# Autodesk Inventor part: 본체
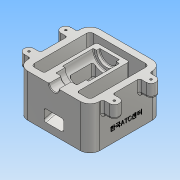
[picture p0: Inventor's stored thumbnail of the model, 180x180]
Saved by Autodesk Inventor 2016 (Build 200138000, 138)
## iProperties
Created: 2018-01
Part Number: 본체
Material: 알루미늄 6061
Document SubType Name: Modeling
Designer: Administrator
Density: 2.7 g/cm^3
Appearance: 알루미늄 - 평지
Mass: 994.61 g
Surface Area: 834.489 cm^2
Volume: 368.374 cm^3
Author: Administrator
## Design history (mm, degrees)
sketch "스케치1"
  geometry: L1 (-55, -55)-(55, -55); L2 (55, -55)-(55, -35.5); L3 (55, 55)-(-55, 55); L4 (-55, 55)-(-55, 35.5); L5 (-55, -55)-(55, 55); L6 (55, -55)-(-55, 55); L7 (-65, -20.5)-(-55, -20.5); L8 (-55, -20.5)-(-55, -35.5); L9 (-55, -35.5)-(-65, -35.5); L10 (-65, -35.5)-(-65, -20.5); L11 (-65, 20.5)-(-55, 20.5); L12 (-55, 20.5)-(-55, 35.5); L13 (-55, 35.5)-(-65, 35.5); L14 (-65, 35.5)-(-65, 20.5); L15 (0, 55)-(0, -55); L16 (55, 35.5)-(65, 35.5); L17 (65, 20.5)-(55, 20.5); L18 (65, -20.5)-(55, -20.5); L19 (55, -35.5)-(65, -35.5); L20 (65, -35.5)-(65, -20.5); L21 (65, 35.5)-(65, 20.5); L22 (-55, 35.5)-(-55, 20.5); L23 (-55, 20.5)-(-55, -20.5); L24 (-55, -20.5)-(-55, -35.5); L25 (-55, -35.5)-(-55, -55); L26 (55, -35.5)-(55, -20.5); L27 (55, -20.5)-(55, 20.5); L28 (55, 20.5)-(55, 35.5); L29 (55, 35.5)-(55, 55); A1 r 7.5 centre (-65, -28) between (-65, -20.5) and (-65, -35.5); A2 r 7.5 centre (-65, 28) between (-65, 35.5) and (-65, 20.5); A3 r 7.5 centre (65, -28) between (65, -35.5) and (65, -20.5); A4 r 7.5 centre (65, 28) between (65, 20.5) and (65, 35.5); 3 further points
  constraints: 58 end point, 30 parallel, 10 symmetric about line, 9 midpoint, 8 point on circle, 7 perpendicular, 4 centre point, 4 point on line, 3 horizontal, 2 other
  dimensions: "d0" = 110 distance of L3.end L3.start; "d1" = 110 distance of L3.start L1.end; "d2" = 27 distance of L3.end point (-55, 28); "d3" = 56 distance of point (-55, -28) point (-55, 28); "d4" = 10 distance of L4.end L13.end; "d5" = 7.5 radius of A2; "d6" = 7.5 radius of A1
extrude "돌출1" new body sketch "스케치1" distance "d7" = 65; taper "d8" = 0 deg
sketch "스케치2"
  geometry: L1 (-55, 55)-(-55, -55) reference; L2 (-65, 35.5)-(-55, 35.5); L3 (-55, 35.5)-(-55, 20.5); L4 (-55, 20.5)-(-65, 20.5); L5 (-65, 20.5)-(-65, 35.5); L6 (-65, -20.5)-(-55, -20.5); L7 (-55, -20.5)-(-55, -35.5); L8 (-55, -35.5)-(-65, -35.5); L9 (-65, -35.5)-(-65, -20.5); L10 (0, 0)-(0, 16.819); L11 (55, -35.5)-(65, -35.5); L12 (65, -35.5)-(65, -20.5); L13 (65, -20.5)-(55, -20.5); L14 (55, 20.5)-(65, 20.5); L15 (65, 20.5)-(65, 35.5); L16 (65, 35.5)-(55, 35.5); A1 r 7.5 centre (-65, 28) between (-65, 35.5) and (-65, 20.5); A2 r 7.5 centre (-65, -28) between (-65, -20.5) and (-65, -35.5); A3 r 7.5 centre (65, -28) between (65, -35.5) and (65, -20.5); A4 r 7.5 centre (65, 28) between (65, 20.5) and (65, 35.5); 1 further point
  constraints: 30 end point, 10 symmetric about line, 8 point on circle, 4 centre point, 4 parallel, 4 point on line, 3 midpoint, 2 horizontal, 2 perpendicular, 1 vertical, 2 other
  dimensions: "d9" = 10 distance of L2.start L2.end; "d10" = 7.5 radius of A1; "d11" = 7.5 radius of A2; "d12" = 27 vertical distance of A1.centre L1.start; "d13" = 56 distance of A2.centre A1.centre
extrude "돌출2" join sketch "스케치2" distance "d14" = 20; taper "d15" = 0 deg
feature "쉘1" dims "d16" = 10
sketch "스케치3"
  geometry: L1 (-45, 0)-(-45, 65) reference; L2 (-45, 8.564)-(35, 30); L3 (45, 0)-(-45, 0) reference; L4 (35, 30)-(35, 65); L5 (20.5, 65)-(-20.5, 65) reference; L6 (-55, 0)-(-55, 65) reference; L7 (-45, 8.564)-(-55, 10.787); L8 (35, 65)-(-45, 65); L9 (-35.5, 65)-(-55, 65) reference; L10 (45, 0)-(45, 65) reference; L11 (55, 0)-(55, 65) reference; 1 further point
  constraints: 8 end point, 3 point on line, 1 collinear, 1 vertical
  dimensions: "d17" = 30 distance from line of L3 L2.end; "d18" = 105 deg angle of L1 L2; "d38" = 20 distance between parallel lines of L11 L4
extrude "돌출3" join sketch "스케치3" stored distance "d22" = 50; taper "d23" = 0 deg
sketch "스케치7"
  geometry: L1 (-55, 0)-(-55, 65) reference; L2 (-55, 11.061)-(20, 31.157); L3 (35, 65)-(35, 30) reference; L4 (35, 30)-(-45, 8.564) reference; L5 (-55, 29.061)-(-17, 39.243); L6 (-17, 39.243)-(-17, 57.924); L7 (20, 31.157)-(20, 57.924); L8 (-17, 57.924)-(-17, 63.66); L9 (20, 57.924)-(20, 63.66); L10 (-17, 63.66)-(20, 63.66); L11 (20.5, 65)-(-20.5, 65) reference; L12 (-55, 29.061)-(-55, 11.061); 1 further point
  constraints: 16 end point, 4 vertical, 2 point on line, 1 collinear, 1 parallel
  dimensions: "d33" = 15 distance from line of L3 L2.end; "d34" = 5 distance between parallel lines of L4 L2; "d35" = 18 distance of L2.start L5.start; "d36" = 75 deg angle of L5 L1; "d37" = 37 distance between parallel lines of L6 L7
extrude "돌출4" cut sketch "스케치7" stored distance "d39" = 30; taper "d40" = 0 deg
sketch "스케치9"
  geometry: L1 (-25, 35)-(25, 35) reference; L2 (-55, -55)-(55, -55) reference; L3 (0, 35)-(0, -55); L4 (-55, -55)-(55, -55) reference; L5 (-7.5, -55)-(-7.5, -36); L6 (-16, -22)-(-16, -36); L7 (-20, 25)-(-20, -22); L8 (-15, 30)-(-15, 25); L9 (-15, 25)-(-20, 25); L10 (-20, -22)-(-16, -22); L11 (-16, -36)-(-7.5, -36); L12 (-15, 30)-(0, 30); L13 (-7.5, -55)-(0, -55); 1 further point
  constraints: 20 end point, 4 perpendicular, 3 vertical, 2 midpoint, 2 point on line, 1 collinear, 1 horizontal
  dimensions: "d41" = 15 diameter of L5 L3; "d42" = 32 diameter of L6 L3; "d43" = 40 diameter of L7 L3; "d44" = 30 diameter of L8 L3; "d45" = 5 distance of L8.start L8.end; "d46" = 47 distance of L7.start L7.end; "d47" = 14 distance of L6.start L6.end; "d48" = 19 distance of L5.start L5.end
revolve "회전1" sketch "스케치9" stored, may be unused: angle "d49" = 90 deg
hole "구멍1" diameter "d52" = 3.242; stored, may be unused: countersink angle "d56" = 90 deg, drill point angle "d58" = 118 deg; dims "d50" = 10, "d51" = 10, "d53" = 9, "d54" = 4, "d55" = 2, "d57" = 11
hole "구멍2" diameter "d61" = 3.242; stored, may be unused: countersink angle "d65" = 90 deg, drill point angle "d67" = 118 deg; dims "d59" = 10, "d60" = 10, "d62" = 9, "d63" = 4, "d64" = 2, "d66" = 11
hole "구멍3" diameter "d70" = 3.242; stored, may be unused: countersink angle "d74" = 90 deg, drill point angle "d76" = 118 deg; dims "d68" = 10, "d69" = 10, "d71" = 9, "d72" = 4, "d73" = 2, "d75" = 11
hole "구멍4" diameter "d79" = 3.242; stored, may be unused: countersink angle "d83" = 90 deg, drill point angle "d85" = 118 deg; dims "d77" = 10, "d78" = 10, "d80" = 9, "d81" = 4, "d82" = 2, "d84" = 11
fillet "모깎기1" dims "d86" = 15
fillet "모깎기2" dims "d87" = 5
fillet "모깎기4" dims "d89" = 3
fillet "모깎기5" dims "d90" = 3
sketch "스케치11"
  geometry: L1 (0, 0)-(0, 80) reference; L2 (-65, -15)-(0, -15) reference; 2 further points
  constraints: 1 other
  dimensions: "d103" = 55 distance from line of L2 point (-20, 40); "d104" = 20 distance from line of L1 point (-20, 40)
feature "엠보싱2" sketch "스케치11" dims "d0" = 110, "d1" = 110, "d2" = 27, "d3" = 56, "d4" = 10, "d5" = 7.5, "d6" = 7.5, "d105" = 0.5, "d106" = 0
fillet "모깎기11" dims "d107" = 1
chamfer "모따기2" distance "d108" = 1; stored, may be unused: second distance "d109" = 2, angle "d110" = 45 deg
chamfer "모따기3" distance "d111" = 1; stored, may be unused: second distance "d112" = 2, angle "d113" = 45 deg
fillet "모깎기12" dims "d114" = 3
fillet "모깎기13" dims "d115" = 3
fillet "모깎기14" dims "d116" = 3
fillet "모깎기15" dims "d117" = 3
fillet "모깎기16" dims "d118" = 3
fillet "모깎기17" dims "d119" = 3
fillet "모깎기18" dims "d120" = 3
node "솔리드1"
mirror "대칭1"
